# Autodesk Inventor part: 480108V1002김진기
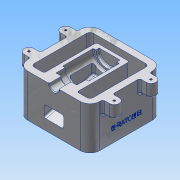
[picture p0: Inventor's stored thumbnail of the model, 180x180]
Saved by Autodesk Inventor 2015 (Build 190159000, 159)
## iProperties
Created: 2018-01
Part Number: 480108V1002김진기
Material: 알루미늄 6061
Document SubType Name: Modeling
Designer: Administrator
Density: 2.7 g/cm^3
Appearance: 알루미늄 - 평지
Mass: 956.404 g
Surface Area: 819.325 cm^2
Volume: 354.224 cm^3
Author: Administrator
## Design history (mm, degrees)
sketch "스케치1"
  geometry: L1 (-55, 55)-(55, 55); L2 (55, 55)-(55, -55); L3 (55, -55)-(-55, -55); L4 (-55, -55)-(-55, 55); L5 (-35.5, 55)-(-20.5, 55); L6 (35.5, 55)-(20.5, 55); 3 further points
  constraints: 12 end point, 4 point on line, 2 horizontal, 2 midpoint, 2 parallel, 1 collinear, 1 horizontal alignment, 1 perpendicular, 1 vertical alignment
  dimensions: "d0" = 110 distance of L2.end L3.end; "d1" = 110 distance of L3.end L1.start
extrude "돌출1" new body sketch "스케치1" stored distance "d6" = 65; taper "d7" = 0 deg
sketch "스케치3"
  geometry: L1 (-45, 45)-(45, 45); L2 (45, 45)-(45, -45); L3 (45, -45)-(-45, -45); L4 (-45, -45)-(-45, 45); 3 further points
  constraints: 8 end point, 2 midpoint, 2 parallel, 1 horizontal, 1 horizontal alignment, 1 perpendicular, 1 vertical alignment
  dimensions: "d16" = 90 distance of L1.start L1.end; "d17" = 90 distance of L1.end L2.end
extrude "돌출3" cut sketch "스케치3" stored distance "d18" = 20; taper "d19" = 0 deg
sketch "스케치2"
  geometry: L1 (-35.5, 65)-(-35.5, 55); L2 (-35.5, 55)-(-20.5, 55); L3 (-55, 55)-(55, 55) reference; L4 (-20.5, 55)-(-20.5, 65); L5 (20.5, 65)-(20.5, 55); L6 (20.5, 55)-(35.5, 55); L7 (35.5, 55)-(35.5, 65); L8 (0, 0)-(22.613, 0); L9 (20.5, -65)-(20.5, -55); L10 (35.5, -55)-(35.5, -65); L11 (-55, -55)-(55, -55); L12 (-35.5, -65)-(-35.5, -55); L13 (-20.5, -55)-(-20.5, -65); L14 (-35.5, -55)-(-20.5, -55); L15 (20.5, -55)-(35.5, -55); A1 r 7.5 centre (-28, 65) between (-20.5, 65) and (-35.5, 65); A2 r 7.5 centre (28, 65) between (35.5, 65) and (20.5, 65); A3 r 7.5 centre (28, -65) between (20.5, -65) and (35.5, -65); A4 r 7.5 centre (-28, -65) between (-35.5, -65) and (-20.5, -65)
  constraints: 28 end point, 12 symmetric about line, 8 point on circle, 8 point on line, 4 centre point, 3 parallel, 2 perpendicular, 2 tangent, 1 equal radius, 1 horizontal, 1 horizontal alignment, 1 vertical, 2 other
  dimensions: "d8" = 15 diameter of A1; "d9" = 27 horizontal distance of A1.centre L3.start; "d10" = 56 distance of A2.centre A1.centre; "d11" = 10 distance from line of L3 A1.centre
extrude "돌출2" join sketch "스케치2" distance "d12" = 20; taper "d13" = 0 deg
fillet "모깎기1" dims "d14" = 15
fillet "모깎기2" dims "d20" = 5
fillet "모깎기3" dims "d31" = 3
fillet "모깎기4" dims "d32" = 3
fillet "모깎기5" dims "d33" = 3
fillet "모깎기6" dims "d34" = 3
sketch "스케치6"
  geometry: L1 (-45, -40)-(-45, 40) reference; L2 (-45, 25)-(35, 25); L3 (35, 25)-(35, -25); L4 (35, -25)-(-45, -25); L5 (-45, -25)-(-45, 25); L6 (55, -40)-(55, 40) reference; 4 further points
  constraints: 8 end point, 3 midpoint, 2 parallel, 1 horizontal, 1 horizontal alignment, 1 perpendicular, 1 point on line, 1 vertical alignment
  dimensions: "d35" = 50 distance of L2.end L3.end; "d36" = 20 distance between parallel lines of L6 L3
extrude "돌출5" join sketch "스케치6" distance "d37" = 30; taper "d38" = 0 deg
sketch "스케치7"
  geometry: L1 (-35, 2.5)-(45, -18.936); L2 (45, -18.936)-(45, 2.5); L3 (45, 32.5)-(45, -32.5) reference; L4 (45, 2.5)-(-35, 2.5); L5 (45, 2.5)-(-35, 2.5) reference; 1 further point
  constraints: 6 end point, 2 collinear
  dimensions: "d39" = 105 deg angle of L3 L1
extrude "돌출6" join sketch "스케치7" stored distance "d40" = 50; taper "d41" = 0 deg
sketch "스케치8"
  geometry: 1 further point
fillet "모깎기7" dims "d42" = 3
fillet "모깎기8" dims "d43" = 3
sketch "스케치9"
  geometry: L1 (-32.776, 1.904)-(42.776, -18.34) reference; L2 (-20, 3.657)-(58.517, -17.381); L3 (-20, 3.657)-(-20, 23.44); L4 (-20, 23.44)-(17, 23.44); L5 (17, 23.44)-(17, 11.743); L6 (17, 11.743)-(58.517, 0.619); L7 (58.517, -17.381)-(58.517, 0.619); L8 (-55, 32.5)-(-55, -32.5) reference; L9 (55, -32.5)-(55, 32.5) reference; 2 further points
  constraints: 12 end point, 2 parallel, 2 vertical, 1 horizontal, 1 perpendicular
  dimensions: "d44" = 5 distance between parallel lines of L1 L2; "d45" = 18 distance of L2.end L6.end; "d46" = 37 distance of L3.end L4.end; "d66" = 11.69695 distance of L4.end L5.end; "d102" = 35 distance between parallel lines of L8 L3; "d103" = 41.51683 distance between parallel lines of L5 L7
extrude "돌출7" cut sketch "스케치9" stored distance "d50" = 30; taper "d51" = 0 deg
sketch "스케치10"
  geometry: L1 (55, 32.5)-(55, 25); L2 (55, 25)-(36, 25); L3 (36, 25)-(36, 16.5); L4 (36, 16.5)-(22, 16.5); L5 (22, 16.5)-(22, 12.5); L6 (22, 12.5)-(-25, 12.5); L7 (-25, 12.5)-(-25, 16.5); L8 (-25, 16.5)-(-30, 16.5); L9 (55, 32.5)-(-30, 32.5); L10 (40, 32.5)-(-40, 32.5) reference; L11 (-30, 32.5)-(-30, 16.5); 2 further points
  constraints: 20 end point, 5 perpendicular, 3 vertical, 1 horizontal alignment, 1 point on line
  dimensions: "d55" = 19 distance of L1.end L2.end; "d56" = 14 distance of L3.end L4.end; "d57" = 47 distance of L5.end L6.end; "d59" = 5 distance of L7.end L8.end; "d60" = 15 diameter of L2 L9; "d61" = 32 diameter of L4 L9; "d62" = 40 diameter of L6 L9
revolve "회전1" sketch "스케치10" stored, may be unused: angle "d63" = 90 deg
chamfer "모따기1" distance "d68" = 1; stored, may be unused: second distance "d69" = 2, angle "d70" = 45 deg
fillet "모깎기9" dims "d71" = 1
sketch "스케치11"
  geometry: L1 (55, -40)-(55, 40) reference; L2 (40, 55)-(38.5, 55) reference; L3 (-55, 40)-(-55, 8.5) reference; L4 (38.5, -55)-(40, -55) reference; 5 further points
  constraints: 2 horizontal alignment, 2 vertical alignment
  dimensions: "d76" = 27 distance from line of point (28, 65) L1; "d77" = 10 distance from line of point (28, 65) L2; "d78" = 27 distance from line of L3 point (-28, 65); "d79" = 10 distance from line of L4 point (28, -65)
hole "구멍1" sketch "스케치11" at (28, 65), (-28, 65), (-28, -65), (28, -65) diameter "d81" = 3.242; stored, may be unused: countersink angle "d85" = 90 deg, drill point angle "d87" = 118 deg; dims "d82" = 9, "d83" = 4, "d84" = 2, "d86" = 11
sketch "스케치12"
  geometry: L1 (16.136, 23.377)-(63.864, 23.377); L2 (63.864, 23.377)-(63.864, 16.623); L3 (63.864, 16.623)-(16.136, 16.623); L4 (16.136, 16.623)-(16.136, 23.377); L5 (-15, 65)-(-15, 0) reference; L6 (95, 0)-(80, 0) reference; 4 further points
  constraints: 2 midpoint, 1 horizontal alignment, 1 vertical alignment, 2 other
  dimensions: "d88" = 55 distance from line of L5 point (40, 20); "d89" = 20 distance from line of L6 point (40, 20); "d90" = 47.72772 distance of L1.start L1.end; "d91" = 6.75365 distance of L1.end L2.end; "d92" = 23.86386 horizontal distance of point (40, 23.377) point (63.864, 20)
feature "엠보싱1" sketch "스케치12" dims "d0" = 110, "d1" = 110, "d8" = 15, "d9" = 27, "d10" = 56, "d11" = 10, "d93" = 0.5, "d94" = 0
fillet "모깎기14" dims "d95" = 3
fillet "모깎기15" dims "d96" = 3
fillet "모깎기16" dims "d97" = 3
fillet "모깎기17" dims "d98" = 3
node "솔리드1"
